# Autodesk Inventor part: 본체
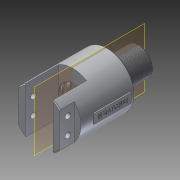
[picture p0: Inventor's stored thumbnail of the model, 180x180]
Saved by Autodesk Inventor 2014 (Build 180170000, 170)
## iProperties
Created: 2019-02
Part Number: 본체
Material: 알루미늄 6061
Document SubType Name: Modeling
Designer: OA55
Density: 2.71 g/cm^3
Appearance: 알루미늄 - 평지
Mass: 347.129 g
Surface Area: 298.285 cm^2
Volume: 128.092 cm^3
Author: OA55
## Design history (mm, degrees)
sketch "스케치1"
  geometry: L1 (0, 54)-(0, -54); L2 (0, 54)-(29, 54); L3 (29, 54)-(29, -20); L4 (29, -20)-(13, -20); L5 (13, -20)-(13, -25); L6 (13, -25)-(15, -25); L7 (15, -25)-(15, -54); L8 (15, -54)-(0, -54); L9 (0, 54)-(0, -54); 2 further points
  constraints: 18 end point, 5 parallel, 2 perpendicular, 1 coincident, 1 collinear, 1 midpoint, 1 vertical
  dimensions: "d0" = 108 distance of L1.start L1.end; "d1" = 58 diameter of L3 L1; "d2" = 74 distance of L2.end L3.end; "d3" = 5 distance of L4.end L5.end; "d4" = 26 diameter of L5 L1; "d5" = 30 diameter of L7 L1
revolve "회전1" sketch "스케치1" stored, may be unused: angle "d6" = 90 deg
feature "스레드1" dims "d7" = 10, "d8" = 0
node "작업 평면1"
sketch "스케치2"
  geometry: L1 (15, 54)-(-15, 54); L2 (-15, 54)-(-15, 18); L3 (-15, 18)-(15, 18); L4 (15, 18)-(15, 54); L5 (-29, 54)-(29, 54) reference; 2 further points
  constraints: 8 end point, 2 midpoint, 2 parallel, 1 horizontal, 1 perpendicular
  dimensions: "d10" = 30 distance of L3.end L2.end; "d11" = 36 distance of L2.end L1.end
extrude "돌출1" cut sketch "스케치2" stored distance "d12" = 10; taper "d13" = 0 deg
node "작업 평면2"
sketch "스케치3"
  geometry: L1 (-24.819, 54)-(24.819, 54) reference; C1 r 3 at (9, 45); C2 r 3 at (-9, 45); 1 further point
  constraints: 2 centre point
  dimensions: "d15" = 6 diameter of C1; "d16" = 6 diameter of C2; "d17" = 18 distance of C2.centre C1.centre; "d18" = 9 horizontal distance of point (0, 0) C1.centre; "d19" = 9 distance from line of L1 C2.centre; "d20" = 9 distance from line of L1 C1.centre
extrude "돌출2" cut sketch "스케치3" stored distance "d21" = 10; taper "d22" = 0 deg
node "작업 평면3"
sketch "스케치4"
  geometry: L1 (-22, 29.298)-(-22, -29.298); L2 (-22, -29.298)-(-31.8, -29.298); L3 (-31.8, -29.298)-(-31.8, 29.298); L4 (-31.8, 29.298)-(-22, 29.298); C1 r 22 at (0, 0); 2 further points
  constraints: 8 end point, 2 parallel, 1 centre point, 1 coincident, 1 horizontal alignment, 1 midpoint, 1 perpendicular, 1 vertical
  dimensions: "d24" = 44 diameter of C1; "d25" = 9.80035 distance of L3.end L1.start; "d26" = 58.59604 distance of L2.end L3.end; "d27" = 22 horizontal distance of point (0, 0) L1.start
chamfer "모따기1" distance "d28" = 1; stored, may be unused: second distance "d29" = 2, angle "d30" = 45 deg
extrude "돌출3" cut sketch "스케치4" distance "d31" = 16; taper "d32" = 0 deg
chamfer "모따기2" distance "d33" = 1; stored, may be unused: second distance "d34" = 2, angle "d35" = 45 deg
sketch "스케치5"
  geometry: C1 r 14 at (0, 0) reference; C2 r 4 at (0, 0)
  constraints: 1 centre point, 1 coincident
  dimensions: "d36" = 8 diameter of C2
extrude "돌출4" cut sketch "스케치5" stored distance "d37" = 10; taper "d38" = 0 deg
sketch "스케치6"
  geometry: C1 r 14 at (0, 0) reference; 1 further point
  constraints: 1 coincident
hole "구멍1" sketch "스케치6" at (0, 0) diameter "d39" = 12.376; stored, may be unused: countersink angle "d43" = 90 deg, drill point angle "d45" = 0 deg; dims "d40" = 18, "d41" = 4, "d42" = 2, "d44" = 22
node "작업 평면4"
sketch "스케치7"
  geometry: 1 further point
sketch "스케치11"
  geometry: C1 r 4 at (0, 0) reference; C2 r 14 at (0, 0); A1 r 29 centre (0, 0) between (-15, -24.819) and (15, -24.819) reference
  constraints: 1 centre point, 1 coincident
  dimensions: "d50" = 28 diameter of C2
extrude "돌출5" cut sketch "스케치11" distance "d51" = 20; taper "d52" = 0 deg
node "작업 평면5"
sketch "스케치12"
  geometry: C1 r 17 at (0, 0); 1 further point
  constraints: 1 centre point, 1 coincident
  dimensions: "d54" = 34 diameter of C1
extrude "돌출6" cut sketch "스케치12" stored distance "d55" = 4.7; taper "d56" = 0 deg
node "작업 평면6"
sketch "스케치13"
  geometry: C1 r 17 at (0, 0); 1 further point
  constraints: 1 centre point, 1 coincident
  dimensions: "d58" = 34 diameter of C1
extrude "돌출7" cut sketch "스케치13" stored distance "d59" = 4.7; taper "d60" = 0 deg
node "작업 평면7"
sketch "스케치14"
  geometry: C1 r 16 at (0, 0); 1 further point
  constraints: 1 centre point, 1 coincident
  dimensions: "d62" = 32 diameter of C1
extrude "돌출8" cut sketch "스케치14" distance "d63" = 7; taper "d64" = 0 deg
node "작업 평면8"
sketch "스케치15"
  geometry: L1 (5, 25)-(-5, 25); L2 (-5, 25)-(-5, -15); L3 (-5, -15)-(5, -15); L4 (5, -15)-(5, 25); L5 (-29, -20)-(29, -20) reference; 2 further points
  constraints: 8 end point, 2 parallel, 1 horizontal, 1 midpoint, 1 perpendicular, 1 vertical alignment
  dimensions: "d66" = 10 distance of L3.end L2.end; "d67" = 40 distance of L2.end L1.end; "d68" = 5 distance between parallel lines of L5 L3
extrude "돌출9" join sketch "스케치15" distance "d69" = 1; taper "d70" = 0 deg
sketch "스케치16"
  geometry: L1 (-25, 5)-(-25, -5) reference; L2 (-25, -5)-(15, -5) reference; 2 further points
  constraints: 1 other
  dimensions: "d71" = 20 distance from line of point (-5, 0) L1; "d72" = 5 distance from line of L2 point (-5, 0)
feature "엠보싱1" sketch "스케치16" dims "d0" = 108, "d73" = 0.5, "d74" = 0
chamfer "모따기4" distance "d75" = 1; stored, may be unused: second distance "d76" = 2, angle "d77" = 45 deg
chamfer "모따기5" distance "d78" = 1; stored, may be unused: second distance "d79" = 2, angle "d80" = 45 deg
fillet "모깎기1" dims "d81" = 0.8
sketch "스케치17"
  geometry: L1 (4, -32)-(4, -9) reference; L2 (-6.188, -32)-(6.188, -32) reference; L3 (6.188, -32)-(4, -29.812); L4 (6.188, -32)-(9.282, -32); L5 (4, -29.812)-(4, -32); L6 (6.188, -32)-(4, -32); L7 (0, -24.348)-(0, -33.25); 1 further point
  constraints: 10 end point, 2 perpendicular, 1 collinear, 1 equal length, 1 horizontal, 1 point on line
  dimensions: "d94" = 135 deg angle of L4 L3; "d95" = 8.90214 distance of L7.start L7.end; "d96" = 4 horizontal distance of L1.start L7.end; "d97" = 24.34799 distance of point (0, 0) L7.start
revolve "회전2" sketch "스케치17" stored, may be unused: angle "d98" = 90 deg
node "솔리드1"
mirror "대칭1"
other parameters: "d9" = 29, "d14" = 29, "d23" = 54, "d46" = 0, "d53" = -5, "d57" = -9, "d65" = 29
